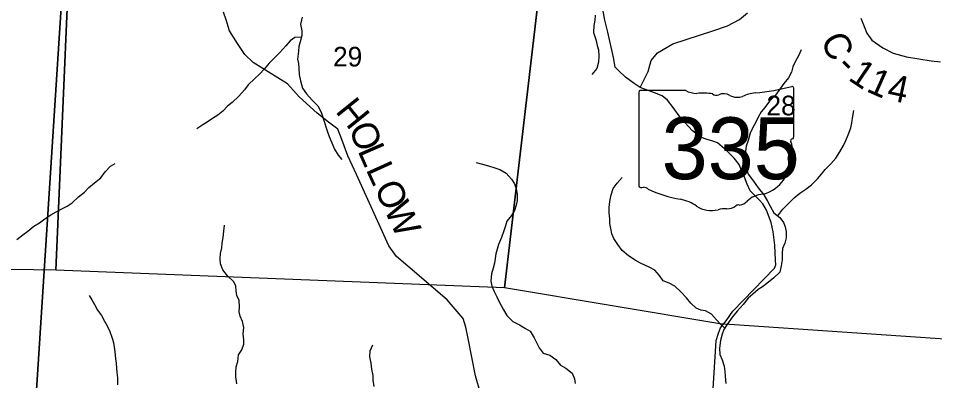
# Model space of a CAD drawing. Extents: x 1578669 to 1989827, y 208020 to 553079.
# Drawn here: x 1860103 to 1870410, y 351046 to 355126 of the extents above; entities that cross this region are included whole.
import ezdxf

# ---------------------------------------------------------------- set-up
doc = ezdxf.new("R2010")
doc.units = 0
for name, color, linetype in [('GM_X_County_Road', 7, 'Continuous'), ('GM_X_County_Road_Text', 7, 'Continuous'), ('GM_X_Minor_River', 7, 'Continuous'), ('GM_X_Section', 7, 'Continuous'), ('GM_X_Section_Text', 7, 'Continuous'), ('GM_X_State_Location', 7, 'Continuous'), ('GM_X_State_Route', 7, 'Continuous'), ('GM_X_State_Shield', 7, 'Continuous'), ('GM_X_Township', 7, 'Continuous')]:
    doc.layers.add(name, color=color, linetype=linetype)

msp = doc.modelspace()

# ---------------------------------------------------------------- linework, layer by layer
at = {"layer": 'GM_X_County_Road'}
for points in [[(1865358, 350712), (1865244, 351101), (1865162, 351521), (1865138, 351648), (1865108, 351745), (1864928, 351958), (1864484, 352335), (1864356, 352444), (1864269, 352566), (1863905, 353369), (1863811, 353578), (1863741, 353761), (1863697, 353879), (1863592, 353958), (1863464, 354057), (1863263, 354244), (1863129, 354389), (1862914, 354522), (1862745, 354629), (1862649, 354720), (1862567, 354843), (1862479, 354986), (1862439, 355108), (1862411, 355197)], [(1867099, 354346), (1867186, 354528), (1867221, 354653), (1867294, 354737), (1867465, 354839), (1867915, 354985), (1868079, 355040), (1868214, 355114), (1868306, 355187)], [(1869579, 355127), (1869647, 354961), (1869704, 354881), (1869825, 354795), (1869943, 354733), (1870094, 354692), (1870369, 354647), (1870476, 354638)]]:
    msp.add_lwpolyline(points, dxfattribs=at)
at = {"layer": 'GM_X_Minor_River'}
for points in [[(1863295, 355138), (1863278, 355060), (1863292, 354986), (1863293, 354932), (1863273, 354860), (1863259, 354808), (1863254, 354756), (1863244, 354668), (1863255, 354618), (1863257, 354564), (1863263, 354492), (1863276, 354423), (1863298, 354341), (1863345, 354277), (1863407, 354204), (1863472, 354140), (1863508, 354070), (1863545, 353955), (1863563, 353903), (1863582, 353847), (1863600, 353795), (1863628, 353723), (1863659, 353652), (1863701, 353586), (1863740, 353536)], [(1866591, 355163), (1866587, 355102), (1866578, 355044), (1866574, 354966), (1866597, 354888), (1866613, 354822), (1866627, 354770), (1866634, 354700), (1866628, 354632), (1866609, 354562), (1866553, 354492)], [(1863288, 354914), (1863213, 354912), (1863159, 354871), (1863113, 354817), (1863046, 354743), (1862924, 354622), (1862869, 354552), (1862817, 354496), (1862761, 354445), (1862690, 354377), (1862646, 354321), (1862585, 354249), (1862507, 354178), (1862455, 354136), (1862402, 354082), (1862348, 354035), (1862288, 353999), (1862238, 353965), (1862178, 353927), (1862109, 353882)], [(1868908, 354772), (1868877, 354704), (1868847, 354650), (1868814, 354579), (1868798, 354521), (1868766, 354457), (1868715, 354393), (1868677, 354341), (1868619, 354261), (1868552, 354192), (1868500, 354124), (1868459, 354072), (1868423, 354014), (1868397, 353956), (1868360, 353888), (1868336, 353833), (1868313, 353751), (1868291, 353687), (1868283, 353631), (1868276, 353561), (1868278, 353507), (1868288, 353440), (1868313, 353372), (1868371, 353292), (1868424, 353219), (1868488, 353139), (1868529, 353069), (1868559, 353010), (1868600, 352938), (1868670, 352882), (1868708, 352829), (1868727, 352777), (1868741, 352721), (1868738, 352655), (1868726, 352595), (1868700, 352533), (1868695, 352479), (1868693, 352407), (1868685, 352341), (1868668, 352269), (1868600, 352203), (1868523, 352140), (1868473, 352102), (1868423, 352074), (1868365, 352020), (1868314, 351977), (1868256, 351903), (1868190, 351829), (1868135, 351765), (1868071, 351676), (1868040, 351622), (1868020, 351570), (1868000, 351500), (1867991, 351412), (1867995, 351342), (1868020, 351282), (1868042, 351209), (1868049, 351151), (1868053, 351097), (1868061, 351015)], [(1868644, 352903), (1868702, 352977), (1868763, 353039), (1868831, 353107), (1868894, 353156), (1868962, 353204), (1869024, 353252), (1869092, 353319), (1869137, 353373), (1869179, 353425), (1869243, 353489), (1869298, 353551), (1869342, 353622), (1869385, 353694), (1869409, 353750), (1869437, 353816), (1869468, 353892), (1869478, 353950), (1869491, 354024), (1869499, 354090)], [(1860085, 352635), (1860155, 352687), (1860211, 352730), (1860279, 352785), (1860343, 352824), (1860402, 352869), (1860467, 352912), (1860530, 352949), (1860585, 352978), (1860653, 353010), (1860710, 353047), (1860779, 353116), (1860848, 353169), (1860896, 353222), (1860961, 353275), (1861030, 353332), (1861079, 353397), (1861138, 353460), (1861191, 353493)], [(1865253, 353503), (1865323, 353484), (1865391, 353464), (1865463, 353443), (1865519, 353423), (1865591, 353382), (1865650, 353316), (1865684, 353264), (1865703, 353206), (1865713, 353145), (1865713, 353075), (1865702, 353021), (1865684, 352963), (1865652, 352906), (1865599, 352844), (1865583, 352788), (1865564, 352734), (1865536, 352658), (1865504, 352580), (1865489, 352526), (1865473, 352474), (1865465, 352422), (1865458, 352370), (1865444, 352312), (1865424, 352250), (1865417, 352168), (1865429, 352112), (1865456, 352052), (1865484, 351989), (1865512, 351935), (1865555, 351853), (1865597, 351779), (1865664, 351712), (1865742, 351676), (1865808, 351635), (1865859, 351603), (1865907, 351530), (1865962, 351418), (1866008, 351358), (1866080, 351333), (1866149, 351283), (1866203, 351220), (1866263, 351186), (1866334, 351131), (1866358, 351067), (1866367, 351013)], [(1868049, 351637), (1868003, 351680), (1867957, 351732), (1867900, 351797), (1867832, 351831), (1867780, 351842), (1867726, 351864), (1867668, 351920), (1867617, 351981), (1867553, 352047), (1867488, 352110), (1867424, 352144), (1867356, 352169), (1867313, 352231), (1867261, 352289), (1867207, 352320), (1867103, 352368), (1867042, 352403), (1866966, 352453), (1866896, 352512), (1866847, 352578), (1866801, 352648), (1866778, 352701), (1866766, 352761), (1866758, 352815), (1866755, 352869), (1866749, 352935), (1866748, 352997), (1866758, 353065), (1866770, 353139), (1866795, 353211), (1866837, 353271), (1866894, 353333)], [(1862559, 351012), (1862548, 351090), (1862548, 351142), (1862554, 351202), (1862573, 351264), (1862581, 351336), (1862618, 351394), (1862638, 351456), (1862638, 351506), (1862631, 351574), (1862641, 351644), (1862624, 351712), (1862598, 351772), (1862586, 351823), (1862591, 351879), (1862587, 351949), (1862559, 352007), (1862552, 352057), (1862550, 352109), (1862528, 352159), (1862455, 352228), (1862405, 352296), (1862376, 352362), (1862374, 352417), (1862378, 352477), (1862391, 352543), (1862395, 352593), (1862406, 352657), (1862414, 352729)], [(1862414, 352729), (1862422, 352797)], [(1860900, 352005), (1860931, 351955), (1860960, 351904), (1860995, 351841), (1861038, 351782), (1861073, 351717), (1861104, 351665), (1861133, 351600), (1861159, 351525), (1861172, 351475), (1861190, 351370), (1861197, 351292), (1861204, 351242), (1861207, 351188), (1861212, 351137), (1861217, 351079), (1861217, 350999)], [(1864104, 350979), (1864093, 351053), (1864095, 351105), (1864081, 351175), (1864070, 351245), (1864056, 351313), (1864059, 351381), (1864089, 351451)]]:
    msp.add_lwpolyline(points, dxfattribs=at)
at = {"layer": 'GM_X_Section'}
for points in [[(1855700, 357766), (1860738, 357233), (1860524, 352292), (1855214, 352368)], [(1860738, 357233), (1866131, 356864), (1865572, 352090), (1860524, 352292)], [(1866131, 356864), (1871398, 356592), (1871077, 351475), (1867993, 351688), (1865572, 352090)]]:
    msp.add_lwpolyline(points, close=True, dxfattribs=at)
at = {"layer": 'GM_X_State_Route'}
msp.add_lwpolyline([(1867919, 350956), (1867953, 351498), (1867977, 351580), (1868002, 351642), (1868065, 351722), (1868140, 351828), (1868607, 352314), (1868625, 352352), (1868619, 352404), (1868612, 352571), (1868593, 352723), (1868570, 352826), (1868517, 352965), (1868477, 353037), (1868435, 353082), (1868383, 353134), (1868335, 353185), (1868302, 353259), (1868270, 353338), (1868239, 353412), (1868211, 353481), (1868155, 353552), (1868074, 353634), (1867966, 353726), (1867914, 353742), (1867850, 353761), (1867775, 353787), (1867686, 353860), (1867556, 354004), (1867467, 354123), (1867405, 354204), (1867343, 354254), (1867259, 354289), (1867099, 354346), (1867031, 354391), (1866933, 354464), (1866857, 354535), (1866815, 354577), (1866798, 354684), (1866732, 354969), (1866700, 355104), (1866679, 355231)], dxfattribs=at)
at = {"layer": 'GM_X_State_Shield'}
for p, q in [((1867084, 354297), (1867084, 353240)), ((1867610, 354315), (1867101, 354315)), ((1868824, 353789), (1868824, 354341)), ((1868824, 353789), (1868824, 353789))]:
    msp.add_line(p, q, dxfattribs=at)
for centre, major_axis, start_param, end_param in [((1868204, 355756), (1845, 0), 4.814394, 5.042369), ((1868805, 354344), (19.4, 0), 6.141152, 7.989035), ((1867104, 354299), (20.2, 0), 1.712693, 3.28349), ((1867732, 354438), (196, 0), 4.042523, 4.731795), ((1867797, 353722), (702, 0), 1.404758, 1.657858), ((1867956, 354305), (56.4, 0), 3.836095, 5.185415), ((1868039, 354183), (117, 0), 0.950623, 2.079405), ((1868190, 354350), (141, 0), 4.081561, 5.145723), ((1868439, 353992), (371, 0), 1.699011, 2.107814), ((1868819, 353748), (30, 0), 1.883978, 3.671073), ((1868629, 353678), (180, 0), 5.934695, 6.695948), ((1868803, 353786), (20.7, 0), 5.05454, 6.418171), ((1868893, 353557), (131, 0), 2.387724, 3.262537), ((1868307, 353487), (462, 0), 5.101752, 6.440018), ((1867104, 353238), (20.3, 0), 3.00124, 4.508301), ((1867107, 353346), (155, 0), 4.665946, 4.897461), ((1867139, 353179), (56, 0), 0.519207, 1.627899), ((1867845, 354129), (1333, 0), 4.195997, 4.488961), ((1868502, 352944), (253, 0), 1.647645, 2.488434), ((1867448, 352766), (417, 0), 0.823519, 1.323587), ((1868071, 353095), (141, 0), 4.691044, 5.507374), ((1868199, 352993), (39.7, 0), 1.147584, 2.315152), ((1868182, 353138), (149, 0), 4.937069, 5.64225), ((1867899, 353174), (265, 0), 4.026481, 4.996735), ((1868052, 352809), (217, 0), 1.495662, 1.94098)]:
    msp.add_ellipse(centre, major_axis=major_axis, ratio=0.8, start_param=start_param, end_param=end_param, dxfattribs=at)
at = {"layer": 'GM_X_Township'}
for points in [[(1859031, 376400), (1860929, 376281), (1862026, 376219), (1861697, 371439), (1861646, 370711), (1861409, 367951), (1861213, 364441), (1861197, 363836), (1861046, 362151), (1860710, 357224), (1860706, 357161), (1860651, 356303), (1860040, 346806)], [(1882647, 364366), (1882063, 357591), (1881945, 356213), (1881936, 356109), (1881811, 354649), (1881526, 351343), (1881415, 350049), (1881322, 347941), (1881166, 345493), (1878346, 345682), (1874430, 345924), (1871549, 346086), (1870033, 346179), (1867333, 346362), (1865771, 346465), (1860040, 346806), (1860651, 356303), (1860706, 357161), (1860710, 357224), (1861046, 362151)]]:
    msp.add_lwpolyline(points, dxfattribs=at)

# ---------------------------------------------------------------- texts
at = {"layer": 'GM_X_County_Road_Text'}
for s, rotation, p in [('C', 295.1459, (1869121, 354884)), ('-', 314.1157, (1869287, 354572)), ('1', 326.1721, (1869426, 354439)), ('1', 336.049, (1869629, 354309)), ('4', 347.9604, (1869862, 354213)), ('H', 308.9511, (1863661, 354077)), ('O', 291.4821, (1863815, 353893)), ('L', 293.6276, (1863916, 353636)), ('L', 294.4072, (1864008, 353426)), ('O', 294.4272, (1864101, 353222)), ('W', 294.7991, (1864211, 352980))]:
    msp.add_text(s, height=300, rotation=rotation, dxfattribs=at).set_placement(p)
at = {"layer": 'GM_X_Section_Text'}
for s, p in [('29', (1863643, 354584)), ('28', (1868518, 354034))]:
    msp.add_text(s, height=221, rotation=0, dxfattribs=at).set_placement(p)
at = {"layer": 'GM_X_State_Location'}
for s in ['s', 'r']:
    msp.add_text(s, height=1, dxfattribs=at).set_placement((1867934, 353698))
msp.add_text('335', height=1, rotation=0, dxfattribs=at).set_placement((1867581, 353626))
at = {"layer": 'GM_X_State_Shield'}
msp.add_text('335', height=696.1, dxfattribs=at).set_placement((1867339, 353315))

doc.saveas('drawing.dxf')
